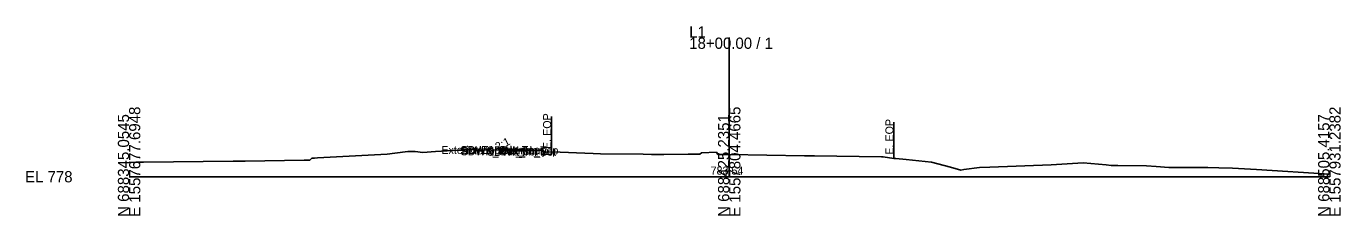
# Model space of a CAD drawing. Extents: x -26 to 2603, y -3010 to 9589.
# Drawn here: x -25.7 to 302.8, y 1490.3 to 1537.5 of the extents above; entities that cross this region are included whole.
import ezdxf

# ---------------------------------------------------------------- set-up
doc = ezdxf.new("R2010")
doc.units = 0
for name, color, linetype in [('Default', 7, 'Continuous'), ('Exist Cross Section Cell', 7, 'Continuous'), ('Exist XS Center Line Elevation Label', 7, 'Continuous'), ('Exist XS Ground Line', 7, 'Continuous'), ('Prop CMT Conc Surface', 7, 'Continuous'), ('Prop CMT Concrete Structures', 7, 'Continuous'), ('Prop CMT Slope Grass', 7, 'Continuous'), ('Prop XS Earthwork Shape', 7, 'Continuous'), ('Prop XS Label Text', 7, 'Continuous'), ('Prop XS Side Slope Text', 7, 'Continuous')]:
    doc.layers.add(name, color=color, linetype=linetype)

msp = doc.modelspace()

# ---------------------------------------------------------------- linework, layer by layer
at = {"layer": 'Exist Cross Section Cell'}
for p, q in [((150, 1500), (150, 1534.68)), ((0, 1500), (150, 1500)), ((150, 1500), (300, 1500))]:
    msp.add_line(p, q, dxfattribs=at)
at = {"layer": 'Exist XS Ground Line'}
msp.add_lwpolyline([(0, 1503.61), (1, 1503.59), (1.34, 1503.59), (1.71, 1503.6), (3.63, 1503.62), (26, 1503.89), (29.05, 1503.87), (43.79, 1504.14), (44.13, 1504.15), (45.14, 1504.1), (45.65, 1504.6), (46.38, 1504.63), (47.09, 1504.68), (64.49, 1505.59), (68.98, 1506.22), (69.71, 1506.27), (71.18, 1506.27), (71.51, 1506.26), (73.43, 1506.08), (76.6, 1506.26), (85.4, 1506.77), (86.05, 1506.74), (100.41, 1506.55), (101.57, 1506.45), (103.17, 1506.62), (103.89, 1506.13), (105.63, 1506.2), (115.98, 1505.79), (117.82, 1505.73), (128.48, 1505.6), (130.54, 1505.58), (133.69, 1505.58), (139.74, 1505.64), (142.63, 1505.65), (143.09, 1505.96), (146.78, 1506.09), (147.17, 1505.58), (150, 1505.54), (168.81, 1505.23), (170.22, 1505.21), (171.28, 1505.19), (188.05, 1504.98), (188.46, 1504.94), (191.14, 1504.57), (191.64, 1504.57), (194.25, 1504.3), (200.57, 1503.65), (205.33, 1502.42), (207.86, 1501.65), (208.61, 1501.8), (212.53, 1502.31), (215.18, 1502.35), (230.48, 1503), (238.48, 1503.5), (244.25, 1502.98), (245.43, 1502.82), (247.17, 1502.84), (254.29, 1502.76), (256.71, 1502.55), (259.88, 1502.34), (269.66, 1502.27), (272.35, 1502.22), (275.83, 1502.13), (281.83, 1501.79), (300, 1500.61)], dxfattribs=at)
at = {"layer": 'Prop CMT Conc Surface'}
for points in [[(98.91, 1506.71), (93.91, 1506.81)], [(103.57, 1506.09), (103.57, 1506.59), (103.07, 1506.59)], [(105.57, 1506.21), (103.57, 1506.09)]]:
    msp.add_lwpolyline(points, dxfattribs=at)
at = {"layer": 'Prop CMT Concrete Structures'}
for points in [[(93.91, 1506.47), (93.91, 1506.81)], [(93.91, 1506.81), (98.91, 1506.71)], [(98.91, 1506.37), (93.91, 1506.47)], [(98.91, 1506.71), (98.91, 1506.37)], [(103.07, 1506.59), (103.07, 1505.57), (105.57, 1505.62)], [(105.57, 1505.62), (105.57, 1506.21)]]:
    msp.add_lwpolyline(points, dxfattribs=at)
at = {"layer": 'Prop CMT Slope Grass'}
for p, q in [((93.41, 1506.82), (93.07, 1506.65)), ((93.91, 1506.81), (93.41, 1506.82)), ((98.91, 1506.71), (103.07, 1506.59))]:
    msp.add_line(p, q, dxfattribs=at)
at = {"layer": 'Prop XS Earthwork Shape'}
for points in [[(93.91, 1506.81), (93.41, 1506.82), (93.07, 1506.65), (93.91, 1506.64)], [(98.91, 1506.37), (93.91, 1506.47), (93.91, 1506.64), (98.91, 1506.57)], [(101.57, 1506.45), (102.89, 1506.59), (98.91, 1506.71), (98.91, 1506.57), (100.41, 1506.55)]]:
    msp.add_lwpolyline(points, close=True, dxfattribs=at)
at = {"layer": 'Prop XS Label Text'}
for p, q in [((105.57, 1514.98), (105.57, 1505.98)), ((191.14, 1513.57), (191.14, 1504.57))]:
    msp.add_line(p, q, dxfattribs=at)

# ---------------------------------------------------------------- texts
at = {"layer": 'Default'}
for s, height, p in [('Exterior Boundary', 2, (78.05, 1505.67)), ('SDWK_Out_Top', 2, (82.83, 1505.67)), ('SDWK_Out_Bot', 2, (82.87, 1505.33)), ('Exterior Boundary', 2, (83.05, 1505.57)), ('SDWK_In_Top', 2, (89.46, 1505.57)), ('SDWK_In_Bot', 2, (89.49, 1505.23)), ('-', 0.0001, (0, 1500))]:
    msp.add_text(s, height=height, dxfattribs=at).set_placement(p)
at = {"layer": 'Exist Cross Section Cell'}
for s, p in [('18+00.00 / 1', (140, 1531.88)), ('L1', (140, 1534.68)), ('EL 778', (-26, 1498.6))]:
    msp.add_text(s, height=2.8, dxfattribs=at).set_placement(p)
for s, p in [('N 688345.0545', (0, 1490)), ('E 1557677.6948', (2.8, 1490)), ('N 688425.2351', (150, 1490)), ('E 1557804.4665', (152.8, 1490)), ('N 688505.4157', (300, 1490)), ('E 1557931.2382', (302.8, 1490))]:
    msp.add_text(s, height=2.8, rotation=90, dxfattribs=at).set_placement(p)
at = {"layer": 'Exist XS Center Line Elevation Label'}
msp.add_text('783.54', height=2, dxfattribs=at).set_placement((145.35, 1500.54))
at = {"layer": 'Prop XS Label Text'}
for p in [(105.47, 1506.91), (191.04, 1505.5)]:
    msp.add_text('E. EOP', height=2, rotation=90, dxfattribs=at).set_placement(p)
at = {"layer": 'Prop XS Side Slope Text'}
msp.add_text('2:1', height=2, rotation=26.8233, dxfattribs=at).set_placement((92.12, 1506.46))

doc.saveas('drawing.dxf')
